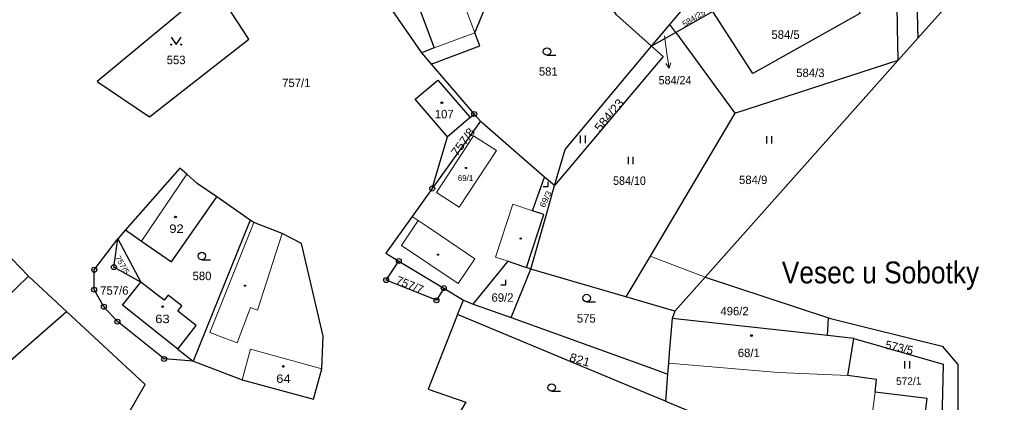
# Model space of a CAD drawing. Extents: x -687135 to -684370, y -1007309 to -1005782.
# Drawn here: x -685221.9 to -685021.3, y -1006674.4 to -1006597.5 of the extents above; entities that cross this region are included whole.
import ezdxf
from ezdxf.enums import TextEntityAlignment as Align

# ---------------------------------------------------------------- set-up
doc = ezdxf.new("R2010")
doc.units = 0
doc.header["$LTSCALE"] = 0.68
for name, color, linetype, lineweight in [('1', 7, 'Continuous', 25), ('3', 7, 'Continuous', 25), ('4', 7, 'Continuous', 13), ('5', 7, 'Continuous', 25), ('7', 7, 'Continuous', 13), ('8', 7, 'Continuous', 25)]:
    doc.layers.add(name, color=color, linetype=linetype, lineweight=lineweight)
doc.layers.add('2', color=7, linetype='Continuous')

msp = doc.modelspace()

# ---------------------------------------------------------------- linework, layer by layer
at = {"layer": '1'}
for p, q in [((-685150.81, -1006589.92), (-685141.03, -1006604.08)), ((-685094.72, -1006602.76), (-685091.03, -1006598.36)), ((-685089.83, -1006600), (-685091.03, -1006598.36)), ((-685089.83, -1006600), (-685094.72, -1006602.76)), ((-685139.08, -1006606.35), (-685130.43, -1006616.41)), ((-685129.19, -1006617.86), (-685138.88, -1006631.41)), ((-685131.25, -1006617.11), (-685135.83, -1006621.02)), ((-685138.88, -1006631.41), (-685135.83, -1006621.02)), ((-685182.28, -1006633.1), (-685186.23, -1006630.42)), ((-685175.53, -1006637.78), (-685182.28, -1006633.1)), ((-685119.91, -1006647.29), (-685116.38, -1006636.65)), ((-685212.49, -1006656.18), (-685220.18, -1006649.03)), ((-685133.76, -1006656.79), (-685132.57, -1006653.88)), ((-685090.57, -1006657.56), (-685091.14, -1006664.47)), ((-685059.27, -1006661.02), (-685059.06, -1006657.45)), ((-685055.2, -1006669.06), (-685053.98, -1006661.6)), ((-685190.1, -1006663.71), (-685187.01, -1006666.15)), ((-685187.01, -1006666.15), (-685192.86, -1006665.72))]:
    msp.add_line(p, q, dxfattribs=at)
for points in [[(-684996.13, -1006550.77), (-684999.43, -1006554.36), (-685002.92, -1006558.42), (-685041.12, -1006601.16), (-685045.06, -1006605.58), (-685083.94, -1006649.24), (-685059.06, -1006657.45)], [(-685136.52, -1006573.27), (-685138.48, -1006582.66), (-685145.19, -1006585.18), (-685138.46, -1006603.11), (-685141.03, -1006604.08), (-685139.08, -1006606.35)], [(-685091.03, -1006598.36), (-685086.48, -1006592.94), (-685085.12, -1006591.49), (-685075.81, -1006579.35)], [(-685139.08, -1006606.35), (-685129.32, -1006602.68), (-685130.31, -1006600.05), (-685128.27, -1006595.15), (-685116.28, -1006587.91), (-685119.66, -1006582.31), (-685111.41, -1006582.43)], [(-685114.27, -1006630.81), (-685112.12, -1006623.52), (-685094.72, -1006602.76), (-685101.78, -1006596.46), (-685111.41, -1006582.43)], [(-685045.06, -1006605.58), (-685045.17, -1006598.99), (-685045.41, -1006584.73), (-685055.1, -1006587.45)], [(-685041.44, -1006586.25), (-685041.16, -1006598.92), (-685041.12, -1006601.16)], [(-685055.1, -1006587.45), (-685052.79, -1006596.21), (-685074.3, -1006608.24), (-685082.35, -1006595.77)], [(-685082.35, -1006595.77), (-685089.83, -1006600), (-685077.97, -1006616.25), (-685045.06, -1006605.58)], [(-685094.72, -1006602.76), (-685092.39, -1006604.84), (-685114.27, -1006630.81)], [(-685135.83, -1006621.02), (-685142.3, -1006613.45), (-685137.75, -1006609.57), (-685131.25, -1006617.11), (-685130.43, -1006616.41)], [(-685130.43, -1006616.41), (-685129.7, -1006617.27), (-685129.19, -1006617.86)], [(-685077.97, -1006616.25), (-685095, -1006645.02), (-685099.87, -1006653.24)], [(-685116.24, -1006629.13), (-685119.83, -1006626.01), (-685128.85, -1006618.16), (-685129.19, -1006617.86)], [(-685186.23, -1006630.42), (-685188.3, -1006628.55), (-685189.73, -1006627.33), (-685200.64, -1006639.74)], [(-685119.03, -1006647.63), (-685115.97, -1006636.81), (-685114.27, -1006630.81), (-685116.24, -1006629.13)], [(-685116.38, -1006636.65), (-685118.7, -1006635.88), (-685116.24, -1006629.13)], [(-685138.88, -1006631.41), (-685142.89, -1006637.01), (-685148.19, -1006644.43), (-685145.6, -1006646)], [(-685200.64, -1006639.74), (-685197.41, -1006641.98), (-685191.35, -1006646.18), (-685182.28, -1006633.1)], [(-685177.15, -1006669.91), (-685162.76, -1006673.81), (-685161.13, -1006667.68), (-685160.82, -1006661.13), (-685165.19, -1006642.44), (-685169.06, -1006640.45), (-685174.82, -1006638.27), (-685175.53, -1006637.78), (-685187.01, -1006666.15)], [(-685244.38, -1006672.48), (-685239.79, -1006668.03), (-685220.18, -1006649.03), (-685225.21, -1006643.84), (-685228.26, -1006639.39)], [(-685200.64, -1006639.74), (-685202.19, -1006641.51), (-685197.53, -1006650.24)], [(-685192.86, -1006665.72), (-685202.26, -1006658.2), (-685204.98, -1006655.2), (-685206.95, -1006651.76), (-685206.92, -1006647.75), (-685202.19, -1006641.51)], [(-685197.53, -1006650.24), (-685202.97, -1006647.23), (-685202.19, -1006641.51)], [(-685136.56, -1006651.46), (-685138.04, -1006653.91), (-685148.15, -1006649.83), (-685145.6, -1006646)], [(-685145.6, -1006646), (-685136.56, -1006651.46), (-685132.57, -1006653.88)], [(-685130.63, -1006654.67), (-685123.61, -1006646.05), (-685122.85, -1006646.3), (-685119.91, -1006647.29)], [(-685130.63, -1006654.67), (-685123, -1006657.37), (-685119.03, -1006647.63), (-685119.91, -1006647.29)], [(-685090.06, -1006656.11), (-685099.87, -1006653.24), (-685119.03, -1006647.63)], [(-685190.1, -1006663.71), (-685201.22, -1006654.91), (-685197.53, -1006650.24)], [(-685190.1, -1006663.71), (-685186.39, -1006658.97), (-685190.1, -1006656.06), (-685189.3, -1006655.03), (-685192.06, -1006652.86), (-685192.87, -1006653.89), (-685197.53, -1006650.24)], [(-685083.94, -1006649.24), (-685090.06, -1006656.11), (-685090.57, -1006657.56)], [(-685132.57, -1006653.88), (-685131.47, -1006654.37), (-685130.63, -1006654.67)], [(-685273.1, -1006707.25), (-685256.03, -1006699.69), (-685252.45, -1006693.52), (-685240.26, -1006683.63), (-685234.38, -1006683.48), (-685227.07, -1006682.77), (-685200.27, -1006677.13), (-685196.71, -1006670.85), (-685212.49, -1006656.18)], [(-685244.38, -1006672.48), (-685237.81, -1006678.26), (-685212.49, -1006656.18)], [(-685133.76, -1006656.79), (-685139.71, -1006671.79), (-685132.11, -1006674.38), (-685135.67, -1006680.29)], [(-685091.94, -1006674.21), (-685095.36, -1006672.8), (-685133.76, -1006656.79)], [(-685123, -1006657.37), (-685093.8, -1006667.91), (-685091.5, -1006668.79)], [(-685053.98, -1006661.6), (-685059.27, -1006661.02), (-685090.57, -1006657.56)], [(-685059.06, -1006657.45), (-685058.68, -1006657.58), (-685036.17, -1006663.13), (-685033.04, -1006666.8), (-685033.04, -1006694.46)], [(-685053.98, -1006661.6), (-685036.02, -1006666.77), (-685036.85, -1006703.99)], [(-685091.14, -1006664.47), (-685091.32, -1006666.58), (-685091.5, -1006668.79), (-685091.94, -1006674.21)], [(-685187.01, -1006666.15), (-685186.07, -1006666.51), (-685177.15, -1006669.91)], [(-685042.21, -1006696.98), (-685039.23, -1006673.64), (-685049.72, -1006672.4), (-685049.41, -1006669.85), (-685055.2, -1006669.06)], [(-685091.94, -1006674.21), (-685084.65, -1006677.21), (-685078.93, -1006683.79)]]:
    msp.add_lwpolyline(points, dxfattribs=at)
msp.add_lwpolyline([(-685206.33, -1006609.89), (-685195.79, -1006616.98), (-685175.8, -1006601.34), (-685182.89, -1006590.44)], close=True, dxfattribs=at)
at = {"layer": '3'}
for p, q in [((-685115.773, -1006604.59), (-685114.023, -1006604.59)), ((-685109.021, -1006622.26), (-685109.021, -1006620.76)), ((-685108.02, -1006622.26), (-685108.02, -1006620.76)), ((-685071.481, -1006622.34), (-685071.481, -1006620.84)), ((-685070.48, -1006622.34), (-685070.48, -1006620.84)), ((-685099.391, -1006626.5), (-685099.391, -1006625)), ((-685098.39, -1006626.5), (-685098.39, -1006625)), ((-685185.263, -1006645.75), (-685183.513, -1006645.75)), ((-685107.783, -1006654.2), (-685106.033, -1006654.2)), ((-685043.691, -1006667.65), (-685043.691, -1006666.15)), ((-685042.69, -1006667.65), (-685042.69, -1006666.15)), ((-685114.833, -1006672.22), (-685113.083, -1006672.22))]:
    msp.add_line(p, q, dxfattribs=at)
for points in [[(-685191.45, -1006600.939), (-685190.45, -1006602.44), (-685189.45, -1006600.939)], [(-685116.521, -1006631.03), (-685115.52, -1006631.03), (-685115.52, -1006630.03)], [(-685125.041, -1006650.76), (-685124.04, -1006650.76), (-685124.04, -1006649.76)]]:
    msp.add_lwpolyline(points, dxfattribs=at)
for centre, radius in [((-685191.45, -1006602.4395), 0.1), ((-685189.45, -1006602.4395), 0.1), ((-685115.7729, -1006603.8398), 0.75), ((-685185.2629, -1006644.9998), 0.75), ((-685107.7829, -1006653.4498), 0.75), ((-685114.8329, -1006671.4698), 0.75)]:
    msp.add_circle(centre, radius, dxfattribs=at)
at = {"layer": '4'}
for p, q in [((-685130.31, -1006600.05), (-685137.04, -1006582.12)), ((-685138.46, -1006603.11), (-685130.31, -1006600.05)), ((-685138, -1006632.2), (-685130.55, -1006620.77)), ((-685125.94, -1006623.78), (-685130.55, -1006620.77)), ((-685197.41, -1006641.98), (-685188.3, -1006628.55)), ((-685126.13, -1006645.2), (-685122.64, -1006634.57)), ((-685122.64, -1006634.57), (-685118.7, -1006635.88)), ((-685174.82, -1006638.27), (-685183.67, -1006660.36)), ((-685145.07, -1006642.86), (-685141.68, -1006637.85)), ((-685141.68, -1006637.85), (-685142.89, -1006637.01)), ((-685141.68, -1006637.85), (-685139.89, -1006639.06)), ((-685174.05, -1006655.89), (-685169.06, -1006640.45)), ((-685137.18, -1006640.89), (-685139.89, -1006639.06)), ((-685130.29, -1006645.54), (-685137.18, -1006640.89)), ((-685145.07, -1006642.86), (-685133.64, -1006650.52)), ((-685133.64, -1006650.52), (-685130.29, -1006645.54)), ((-685123.61, -1006646.05), (-685126.13, -1006645.2)), ((-685095, -1006645.02), (-685083.94, -1006649.24)), ((-685175.45, -1006655.36), (-685178.16, -1006662.46)), ((-685174.05, -1006655.89), (-685175.45, -1006655.36)), ((-685178.16, -1006662.46), (-685183.67, -1006660.36)), ((-685069.19, -1006668.42), (-685091.32, -1006666.58)), ((-685069.19, -1006668.42), (-685055.2, -1006669.06))]:
    msp.add_line(p, q, dxfattribs=at)
for points in [[(-685138, -1006632.2), (-685133.43, -1006635.18), (-685125.94, -1006623.78)], [(-685177.15, -1006669.91), (-685175.47, -1006663.73), (-685161.13, -1006667.68)], [(-685052.69, -1006695.64), (-685051.81, -1006688.73), (-685049.72, -1006672.4)]]:
    msp.add_lwpolyline(points, dxfattribs=at)
at = {"layer": '5'}
for centre, radius in [((-685136.9468, -1006614.1492), 0.175), ((-685132.0948, -1006627.2694), 0.1225), ((-685190.5668, -1006637.1492), 0.175), ((-685121.0648, -1006641.4694), 0.1225), ((-685137.7048, -1006644.7294), 0.1225), ((-685176.5748, -1006650.9494), 0.1225), ((-685193.1468, -1006655.1792), 0.175), ((-685074.6068, -1006660.9992), 0.175), ((-685168.8568, -1006667.2092), 0.175)]:
    msp.add_circle(centre, radius, dxfattribs=at)
at = {"layer": '7'}
msp.add_line((-685091.202, -1006607.192), (-685090.846, -1006606.13), dxfattribs=at)
msp.add_lwpolyline([(-685092.1, -1006600.66), (-685091.62, -1006604.22), (-685091.202, -1006607.192), (-685091.838, -1006606.27)], dxfattribs=at)
at = {"layer": '8'}
for centre, radius in [((-685130.43, -1006616.4099), 0.5), ((-685130.43, -1006616.4099), 0.0303), ((-685138.88, -1006631.4099), 0.5), ((-685138.88, -1006631.4099), 0.0303), ((-685202.97, -1006647.2299), 0.5), ((-685145.6, -1006645.9999), 0.5), ((-685145.6, -1006645.9999), 0.0303), ((-685206.92, -1006647.7499), 0.5), ((-685206.92, -1006647.7499), 0.0303), ((-685202.97, -1006647.2299), 0.0303), ((-685148.15, -1006649.8299), 0.5), ((-685148.15, -1006649.8299), 0.0303), ((-685136.56, -1006651.4599), 0.5), ((-685206.95, -1006651.7599), 0.5), ((-685206.95, -1006651.7599), 0.0303), ((-685136.56, -1006651.4599), 0.0303), ((-685204.98, -1006655.1999), 0.5), ((-685138.04, -1006653.9099), 0.5), ((-685138.04, -1006653.9099), 0.0303), ((-685204.98, -1006655.1999), 0.0303), ((-685202.26, -1006658.1999), 0.5), ((-685202.26, -1006658.1999), 0.0303), ((-685192.86, -1006665.7199), 0.5), ((-685192.86, -1006665.7199), 0.0303)]:
    msp.add_circle(centre, radius, dxfattribs=at)

# ---------------------------------------------------------------- texts
at = {"layer": '2'}
for s, height, rotation, width, p in [('584/25', 1.19, 32, 1.05, (-685088.064, -1006598.954)), ('584/23', 1.7, 50, 1.1, (-685105.068, -1006620.096)), ('757/8', 1.7, 54, 1.1, (-685133.842, -1006625.059)), ('69/3', 1.19, 64, 1.1, (-685116.275, -1006635.35)), ('821', 1.7, 343, 1.1, (-685111.398, -1006666.082))]:
    msp.add_text(s, height=height, rotation=rotation, dxfattribs=dict(at, width=width)).set_placement(p)
for s, height, p in [('584/5', 1.7, (-685070.58, -1006601.28)), ('553', 1.7, (-685192.34, -1006606.37)), ('581', 1.7, (-685117.41, -1006608.7)), ('584/3', 1.7, (-685065.59, -1006608.97)), ('757/1', 1.7, (-685169.09, -1006610.99)), ('107', 1.7, (-685138.36, -1006617.28)), ('69/1', 1.19, (-685133.72, -1006629.905)), ('584/9', 1.7, (-685077.1, -1006630.51)), ('580', 1.7, (-685187.13, -1006649.85)), ('69/2', 1.7, (-685126.94, -1006654.2)), ('575', 1.7, (-685109.76, -1006658.4)), ('496/2', 1.7, (-685080.85, -1006656.929)), ('68/1', 1.7, (-685077.35, -1006665.34))]:
    msp.add_text(s, height=height, dxfattribs=at).set_placement(p)
for s, width, p in [('584/24', 0.95, (-685093.29, -1006610.453)), ('584/10', 0.95, (-685102.47, -1006630.679)), ('92', 1.15, (-685191.82, -1006640.34)), ('63', 1.15, (-685194.65, -1006658.5)), ('64', 1.15, (-685170.29, -1006670.53))]:
    msp.add_text(s, height=1.7, dxfattribs=dict(at, width=width)).set_placement(p)
at = {"layer": '2', "width": 1.05}
msp.add_text('757/5', height=1.139, rotation=300, dxfattribs=at).set_placement((-685201.7632, -1006647.0443), align=Align.CENTER)
at = {"layer": '2'}
for s, rotation, p in [('757/7', 338, (-685146.348, -1006650.528)), ('573/5', 347, (-685047.801, -1006663.608))]:
    msp.add_text(s, height=1.7, rotation=rotation, dxfattribs=at).set_placement(p)
msp.add_text('757/6', height=1.7, dxfattribs=at).set_placement((-685202.89, -1006652.78), align=Align.CENTER)
msp.add_text('572/1', height=1.518, rotation=1, dxfattribs=at).set_placement((-685042.9272, -1006670.9186), align=Align.CENTER)
at = {"layer": '7', "width": 0.9}
msp.add_text('Vesec u Sobotky', height=4.4, dxfattribs=at).set_placement((-685048.62, -1006650.5), align=Align.CENTER)

doc.saveas('drawing.dxf')
